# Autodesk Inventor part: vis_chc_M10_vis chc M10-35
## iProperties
Shininess: 64.0
Length Units: 11269
Angle Units: 11279
Time Units: 11290
Mass Units: 11283
Length Display Precision: 3
Angle Display Precision: 2
Compacted: True
Part Number: vis_chc_M10_vis chc M10-35
Document SubType Name: Modeling
Created: 2006-01
Material: Par défaut
Designer: riri
Density: 0.0
Volumn: 0.0
Area: 0.0
PropertySet Name: Model Information
Control State: 0
Master: False
Checked Out: False
Author: riri
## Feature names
1. Base1
